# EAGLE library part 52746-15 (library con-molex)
FPC Connector ZIF for SMT 0.5mm Source: http://www.farnell.com/datasheets/73044.pdf [DWG. NO. (Sheet 1 OF 2) SD-52746-**17]
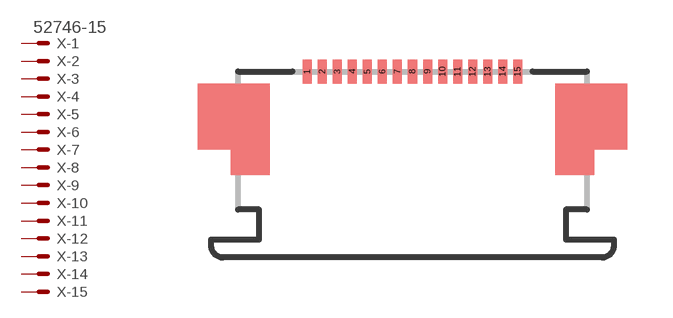
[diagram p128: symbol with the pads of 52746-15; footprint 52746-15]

Designator prefix X; gates -1=MV -2=M -3=M -4=M -5=M -6=M -7=M -8=M -9=M -10=M -11=M -12=M -13=M -14=M -15=M

## 52746-15 (OC_FARNELL: unknown; OC_NEWARK: unknown)  [52746-15]
1  -1:S  pas
2  -2:S  pas
3  -3:S  pas
4  -4:S  pas
5  -5:S  pas
6  -6:S  pas
7  -7:S  pas
8  -8:S  pas
9  -9:S  pas
10  -10:S  pas
11  -11:S  pas
12  -12:S  pas
13  -13:S  pas
14  -14:S  pas
15  -15:S  pas

## Footprint 52746-15 (pad centres in mm)
FPC Connector ZIF for SMT 0.5mm Source: http://www.farnell.com/datasheets/73044.pdf [DWG. NO. (Sheet 1 OF 2) SD-52746-**17]
smd 0.3 x 0.8: 1 -3.5,0.6; 2 -3,0.6; 3 -2.5,0.6; 4 -2,0.6; 5 -1.5,0.6; 6 -1,0.6; 7 -0.5,0.6; 8 0,0.6; 9 0.5,0.6; 10 1,0.6; 11 1.5,0.6; 12 2,0.6; 13 2.5,0.6; 14 3,0.6; 15 3.5,0.6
